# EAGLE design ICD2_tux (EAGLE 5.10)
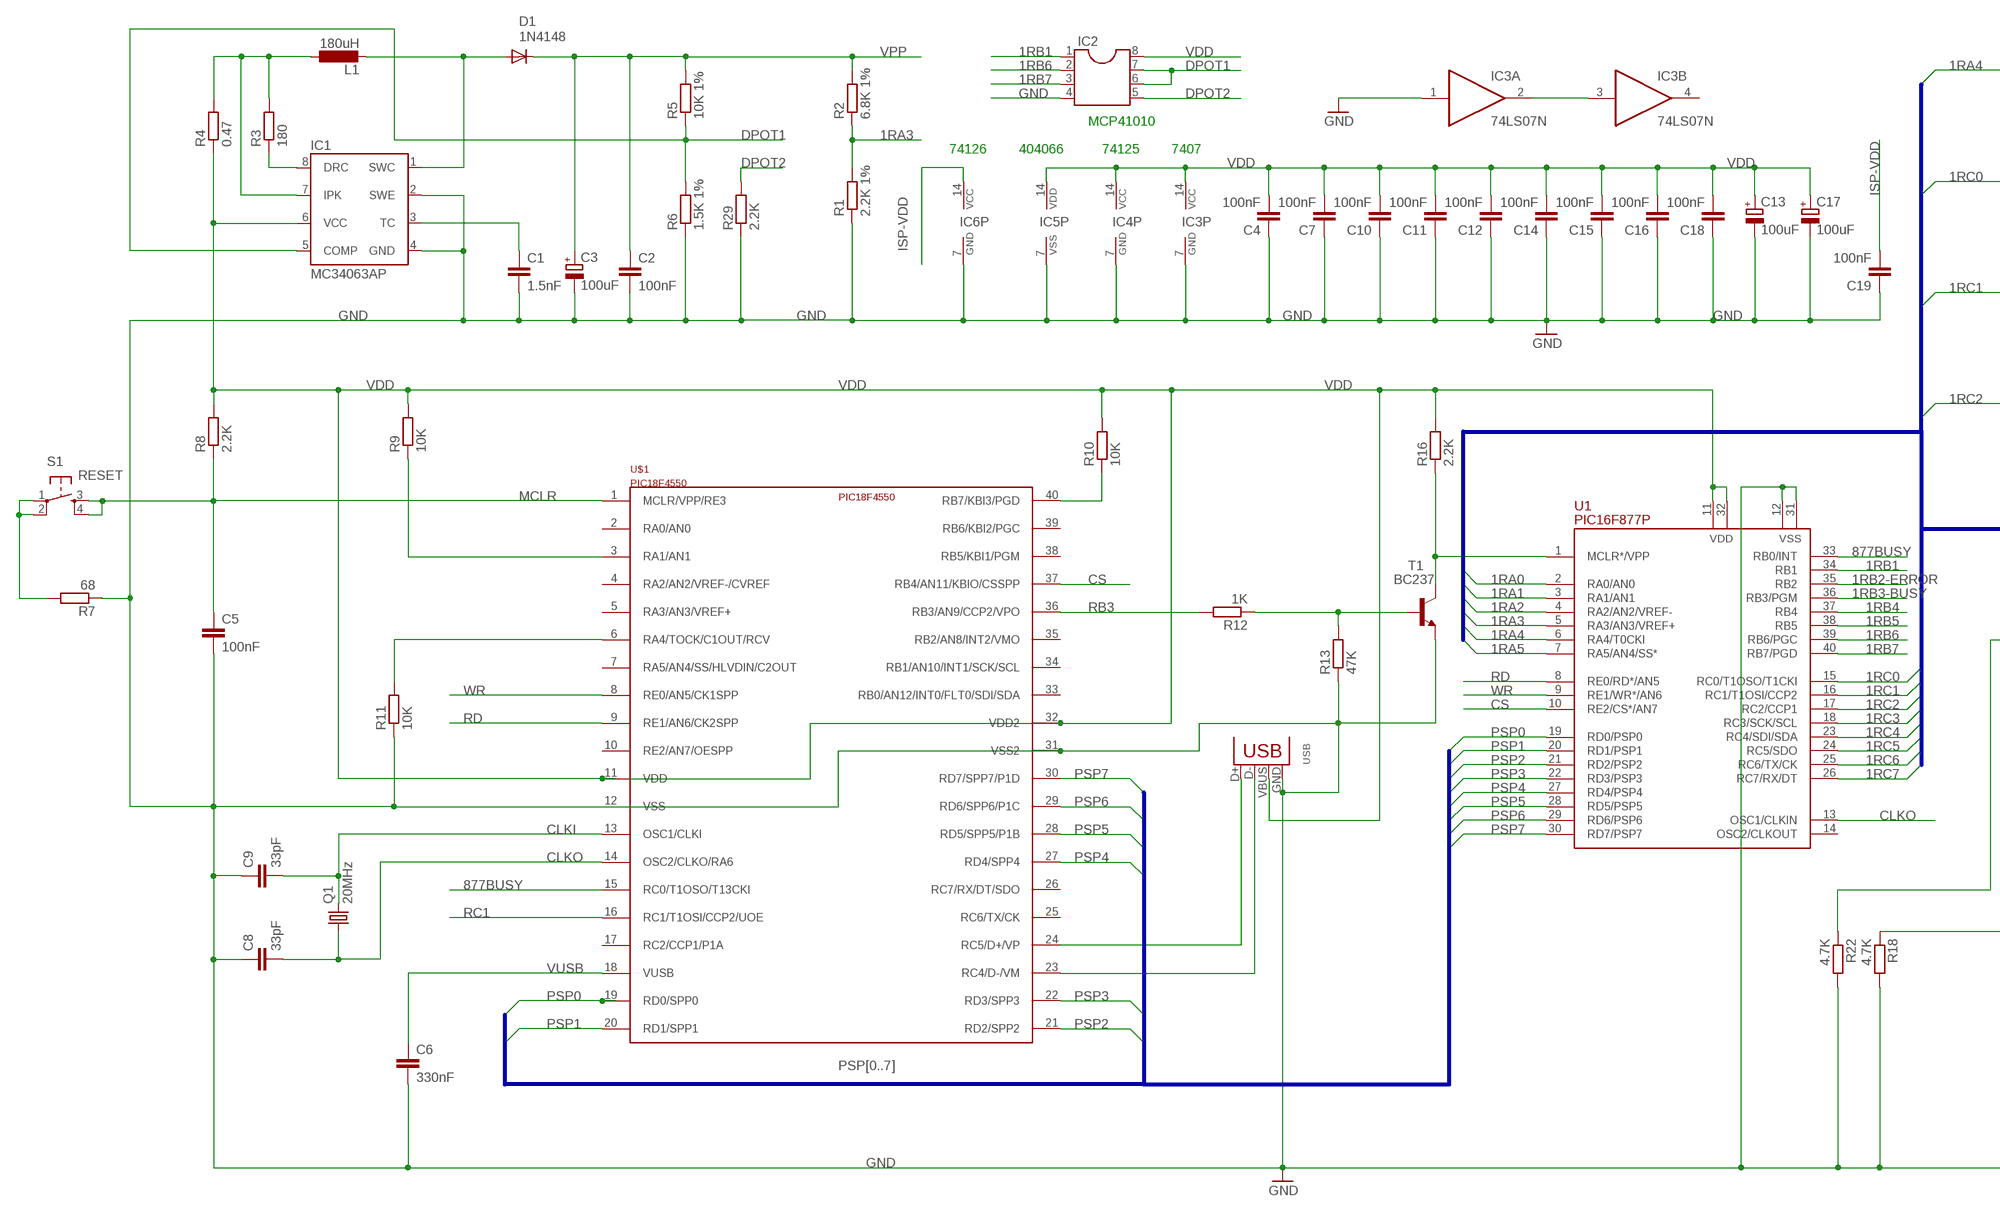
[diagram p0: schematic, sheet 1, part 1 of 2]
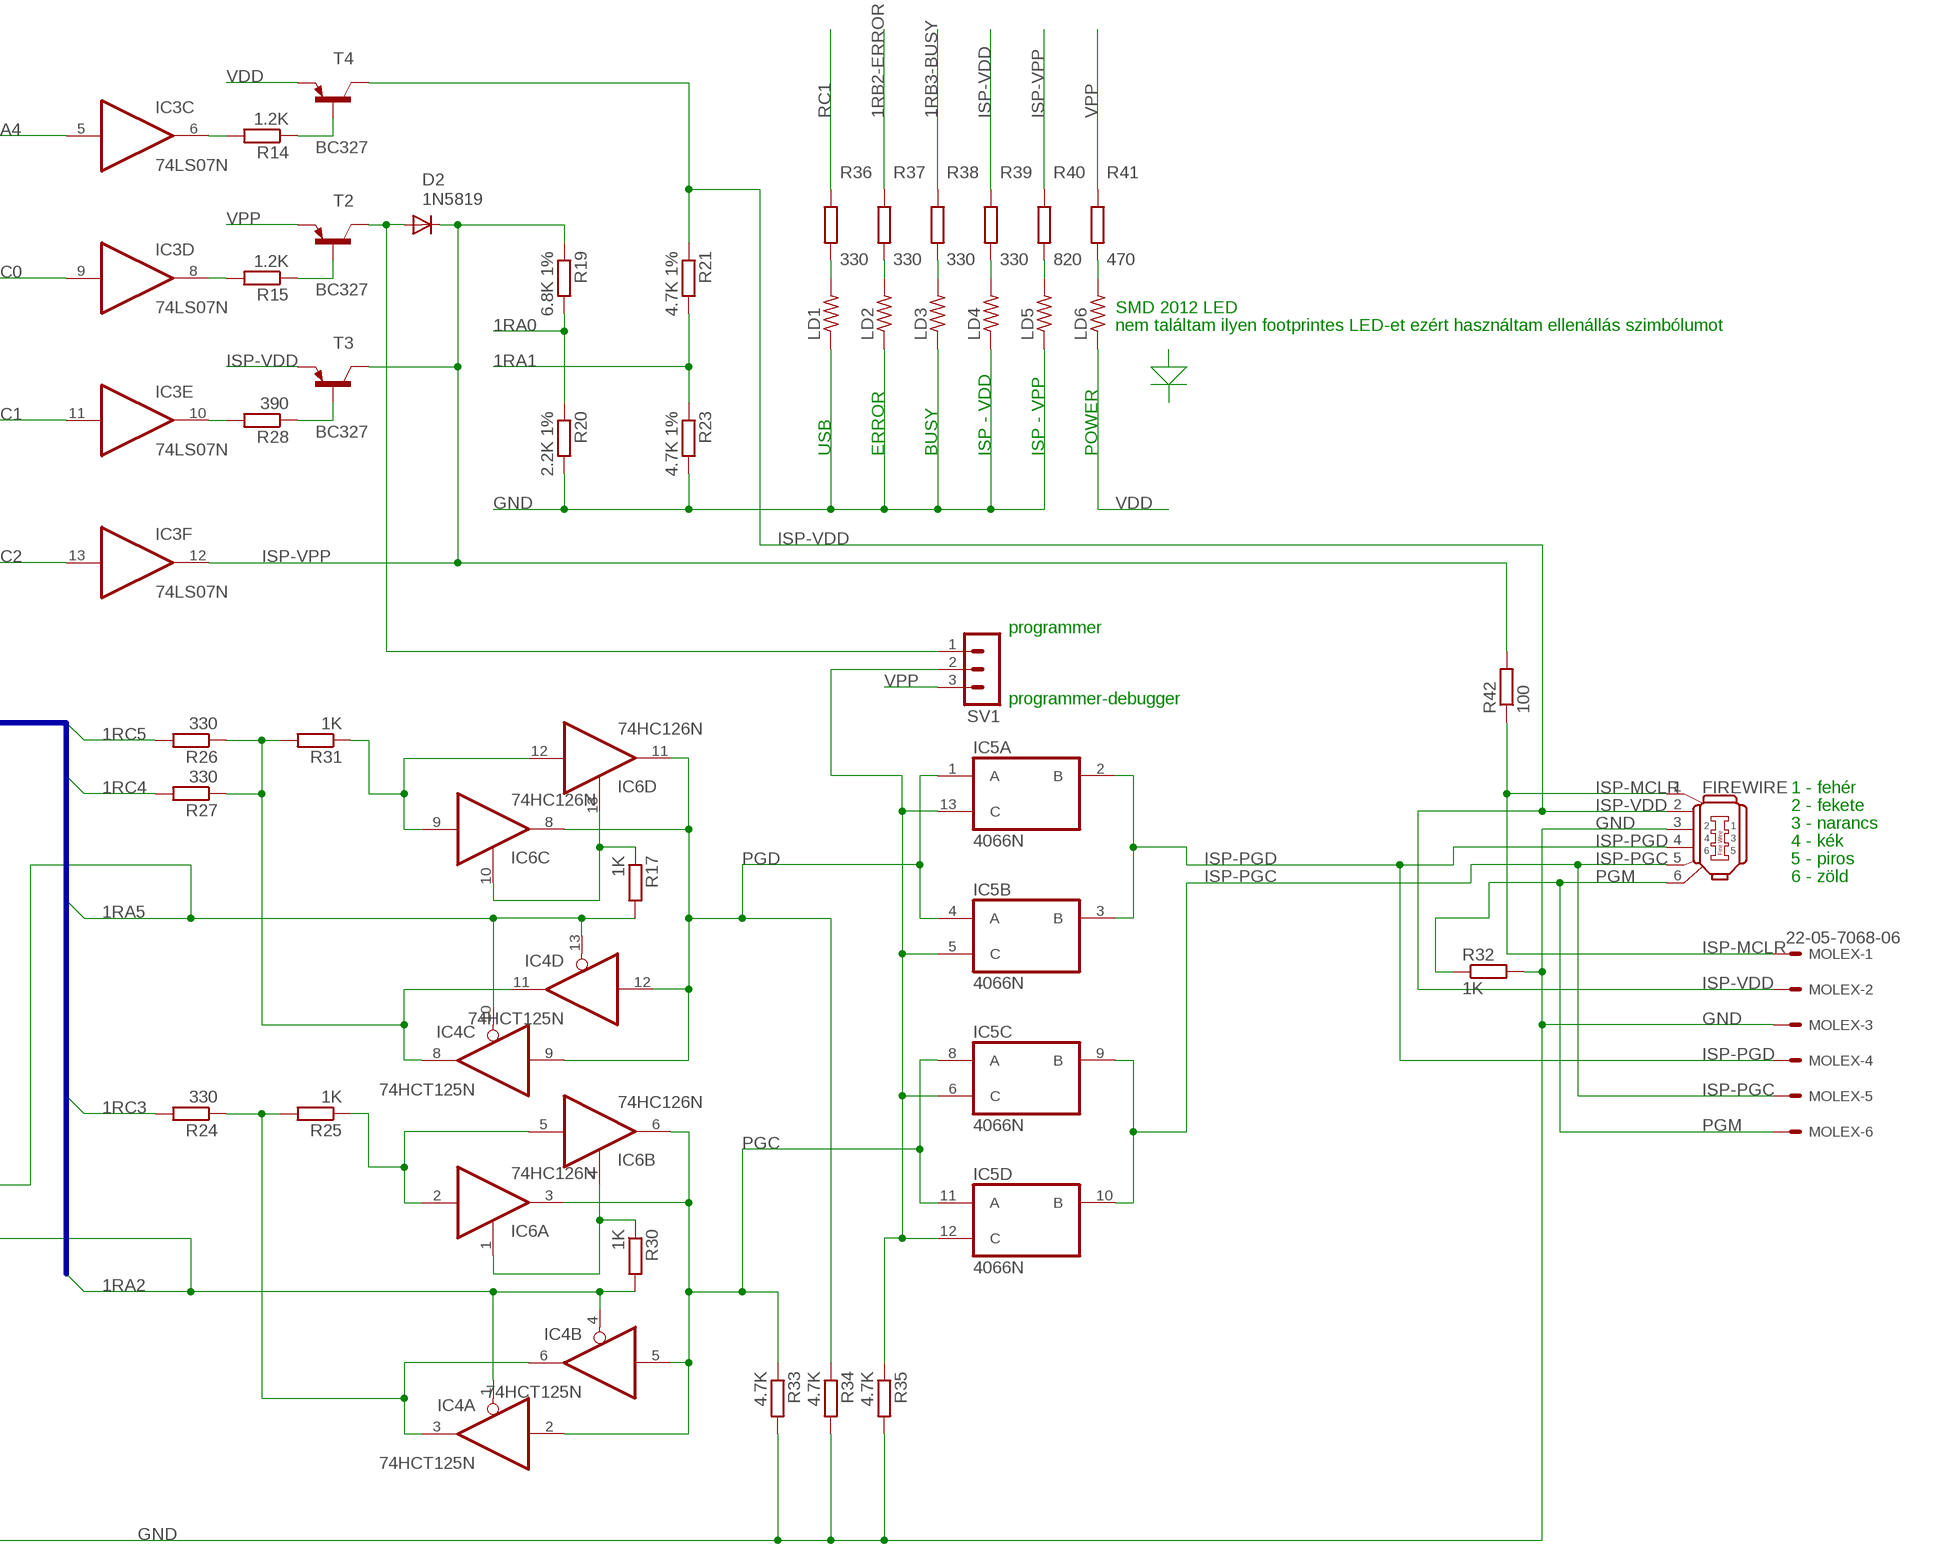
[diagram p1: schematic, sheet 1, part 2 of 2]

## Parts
C1  1.5nF  C-EUC1206  [C1206]
C2  100nF  C-EUC1206  [C1206]
C3  100uF  CPOL-EUE2.5-6  [E2,5-6]
C4  100nF  C-EUC1206  [C1206]
C5  100nF  C-EUC1206  [C1206]
C6  330nF  C-EUC1206  [C1206]
C7  100nF  C-EUC1206  [C1206]
C8  33pF  C-EUC1206  [C1206]
C9  33pF  C-EUC1206  [C1206]
C10  100nF  C-EUC1206  [C1206]
C11  100nF  C-EUC1206  [C1206]
C12  100nF  C-EUC1206  [C1206]
C13  100uF  CPOL-EUE2.5-6  [E2,5-6]
C14  100nF  C-EUC1206  [C1206]
C15  100nF  C-EUC1206  [C1206]
C16  100nF  C-EUC1206  [C1206]
C17  100uF  CPOL-EUE2.5-6  [E2,5-6]
C18  100nF  C-EUC1206  [C1206]
C19  100nF  C-EUC1206  [C1206]
D1  1N4148  DIODE-D-5  [D-5]
D2  1N5819  DIODE-D-5  [D-5]
FIREWIRE  IEEE1394  [IEEE1394]
IC1  MC34063AP  [DIL-08]
IC2  DIL8  [DIL08]
IC3  74LS07N  [DIL14]
IC4  74HCT125N  [DIL14]
IC5  4066N  [DIL14]
IC6  74HC126N  [DIL14]
L1  180uH  L-EU0204/5  [0204/5]
LD1  R-US_M2012  [M2012]
LD2  R-US_M2012  [M2012]
LD3  R-US_M2012  [M2012]
LD4  R-US_M2012  [M2012]
LD5  R-US_M2012  [M2012]
LD6  R-US_M2012  [M2012]
MOLEX  22-05-7068-06  [7395-06]
Q1  20MHz  CRYSTALHC49UP  [HC49UP]
R1  2.2K 1%  R-EU_0204/5  [0204/5]
R2  6.8K 1%  R-EU_0204/5  [0204/5]
R3  180  R-EU_0204/5  [0204/5]
R4  0.47  R-EU_0204/5  [0204/5]
R5  10K 1%  R-EU_0204/5  [0204/5]
R6  1.5K 1%  R-EU_0204/5  [0204/5]
R7  68  R-EU_0204/5  [0204/5]
R8  2.2K  R-EU_0204/5  [0204/5]
R9  10K  R-EU_0204/5  [0204/5]
R10  10K  R-EU_0204/5  [0204/5]
R11  10K  R-EU_0204/5  [0204/5]
R12  1K  R-EU_0204/5  [0204/5]
R13  47K  R-EU_0204/5  [0204/5]
R14  1.2K  R-EU_0204/5  [0204/5]
R15  1.2K  R-EU_0204/5  [0204/5]
R16  2.2K  R-EU_0204/5  [0204/5]
R17  1K  R-EU_0204/5  [0204/5]
R18  4.7K  R-EU_0204/5  [0204/5]
R19  6.8K 1%  R-EU_0204/5  [0204/5]
R20  2.2K 1%  R-EU_0204/5  [0204/5]
R21  4.7K 1%  R-EU_0204/5  [0204/5]
R22  4.7K  R-EU_0204/5  [0204/5]
R23  4.7K 1%  R-EU_0204/5  [0204/5]
R24  330  R-EU_0204/5  [0204/5]
R25  1K  R-EU_0204/5  [0204/5]
R26  330  R-EU_0204/5  [0204/5]
R27  330  R-EU_0204/5  [0204/5]
R28  390  R-EU_0204/5  [0204/5]
R29  2.2K  R-EU_0204/5  [0204/5]
R30  1K  R-EU_0204/5  [0204/5]
R31  1K  R-EU_0204/5  [0204/5]
R32  1K  R-EU_0204/5  [0204/5]
R33  4.7K  R-EU_0204/5  [0204/5]
R34  4.7K  R-EU_0204/5  [0204/5]
R35  4.7K  R-EU_0204/5  [0204/5]
R36  330  R-EU_0204/5  [0204/5]
R37  330  R-EU_0204/5  [0204/5]
R38  330  R-EU_0204/5  [0204/5]
R39  330  R-EU_0204/5  [0204/5]
R40  820  R-EU_0204/5  [0204/5]
R41  470  R-EU_0204/5  [0204/5]
R42  100  R-EU_0204/5  [0204/5]
S1  RESET  DTSM-6  [DTSM-6]
SV1  MA03-1  [MA03-1]
T1  BC237  [TO92]
T2  BC327  [TO92]
T3  BC327  [TO92]
T4  BC327  [TO92]
U1  PIC16F877P  [DIL40]
U$1  PIC18F4550  [PDIP-40]
USB  USB  USB-MB-S  [USB-MB-S]

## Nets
1RA0: R19.2 R20.1 U1.2(RA0/AN0)
1RA1: R21.2 R23.1 U1.3(RA1/AN1)
1RA2: IC4.1(A:OE) IC4.4(B:OE) R18.1 R30.2 U1.4(RA2/AN2/VREF-)
1RA3: R1.2 R2.1 U1.5(RA3/AN3/VREF+)
1RA4: IC3.5(C:I) U1.6(RA4/T0CKI)
1RA5: IC4.10(C:OE) IC4.13(D:OE) R17.2 R22.1 U1.7(RA5/AN4/SS*)
1RB1: IC2.1 U1.34(RB1)
1RB2-ERROR: R37.1 U1.35(RB2)
1RB3-BUSY: R38.1 U1.36(RB3/PGM)
1RB4: U1.37(RB4)
1RB5: U1.38(RB5)
1RB6: IC2.2 U1.39(RB6/PGC)
1RB7: IC2.3 U1.40(RB7/PGD)
1RC0: IC3.9(D:I) U1.15(RC0/T1OSO/T1CKI)
1RC1: IC3.11(E:I) U1.16(RC1/T1OSI/CCP2)
1RC2: IC3.13(F:I) U1.17(RC2/CCP1)
1RC3: R24.2 U1.18(RC3/SCK/SCL)
1RC4: R27.2 U1.23(RC4/SDI/SDA)
1RC5: R26.2 U1.24(RC5/SDO)
1RC6: U1.25(RC6/TX/CK)
1RC7: U1.26(RC7/RX/DT)
877BUSY: U1.33(RB0/INT) U$1.15(RC0/T1OSO/T13CKI)
CLKI: C9.2 Q1.2 U$1.13(OSC1/CLKI)
CLKO: C8.2 Q1.1 U1.13(OSC1/CLKIN) U$1.14(OSC2/CLKO/RA6)
CS: U1.10(RE2/CS*/AN7) U$1.37(RB4/AN11/KBIO/CSSPP)
DPOT1: IC1.5(COMP) IC2.6 IC2.7 R5.1 R6.2
DPOT2: IC2.5 R29.2
GND: C1.2 C2.2 C3.- C4.1 C5.2 C6.2 C7.1 C8.1 C9.1 C10.1 C11.1 C12.1 C13.- C14.1 C15.1 C16.1 C17.- C18.1 C19.1 FIREWIRE.3 IC1.2(SWE) IC1.4(GND) IC2.4 IC3.1(A:I) IC3.7(P:GND) IC4.7(P:GND) IC5.7(P:VSS) IC6.7(P:GND) LD1.1 LD2.1 LD3.1 LD4.1 LD5.1 MOLEX.3 R1.1 R6.1 R7.1 R11.1 R13.1 R18.2 R20.2 R22.2 R23.2 R29.1 R32.2 R33.2 R34.2 R35.2 T1.1(E) U1.12(VSS) U1.31(VSS) U$1.12(VSS) U$1.31(VSS2) USB.GND
ISP-MCLR: FIREWIRE.1 MOLEX.1 R42.1
ISP-PGC: FIREWIRE.5 IC5.9(C:B) IC5.10(D:B) MOLEX.5
ISP-PGD: FIREWIRE.4 IC5.2(A:B) IC5.3(B:B) MOLEX.4
ISP-VDD: C19.2 FIREWIRE.2 IC6.14(P:VCC) MOLEX.2 R21.1 R39.1 T3.1(E) T4.3(C)
ISP-VPP: D2.C IC3.12(F:O) R19.1 R40.1 R42.2 T3.3(C)
MCLR: C5.1 R8.1 S1.3 S1.4 U$1.1(MCLR/VPP/RE3)
N$1: U$1.24(RC5/D+/VP) USB.D+
N$2: U$1.23(RC4/D-/VM) USB.D-
N$3: R10.1 U$1.40(RB7/KBI3/PGD)
N$4: R11.2 U$1.6(RA4/TOCK/C1OUT/RCV)
N$5: R9.1 U$1.3(RA1/AN1)
N$6: IC1.8(DRC) R3.1
N$7: IC1.7(IPK) L1.1 R3.2 R4.2
N$8: D1.A IC1.1(SWC) L1.2
N$9: IC3.2(A:O) IC3.3(B:I)
N$10: C1.1 IC1.3(TC)
N$11: R7.2 S1.1 S1.2
N$12: R12.1 R13.2 T1.2(B)
N$13: R16.1 T1.3(C) U1.1(MCLR*/VPP)
N$14: IC3.6(C:O) R14.2
N$15: IC3.8(D:O) R15.2
N$16: IC3.10(E:O) R28.2
N$17: D2.A SV1.1 T2.3(C)
N$18: R15.1 T2.2(B)
N$19: R14.1 T4.2(B)
N$21: IC6.10(C:OE) IC6.13(D:OE) R17.1
N$22: LD1.2 R36.2
N$23: LD2.2 R37.2
N$24: LD3.2 R38.2
N$25: LD4.2 R39.2
N$26: LD5.2 R40.2
N$27: LD6.2 R41.2
N$28: IC6.2(A:I) IC6.5(B:I) R25.1
N$29: IC6.9(C:I) IC6.12(D:I) R31.1
N$31: IC5.5(B:C) IC5.6(C:C) IC5.12(D:C) IC5.13(A:C) R35.1 SV1.2
N$32: IC6.1(A:OE) IC6.4(B:OE) R30.1
N$33: IC4.8(C:O) IC4.11(D:O) R26.1 R27.1 R31.2
N$37: IC4.3(A:O) IC4.6(B:O) R24.1 R25.2
PGC: IC4.2(A:I) IC4.5(B:I) IC5.8(C:A) IC5.11(D:A) IC6.3(A:O) IC6.6(B:O) R33.1
PGD: IC4.9(C:I) IC4.12(D:I) IC5.1(A:A) IC5.4(B:A) IC6.8(C:O) IC6.11(D:O) R34.1
PGM: FIREWIRE.6 MOLEX.6 R32.1
PSP0: U1.19(RD0/PSP0) U$1.19(RD0/SPP0)
PSP1: U1.20(RD1/PSP1) U$1.20(RD1/SPP1)
PSP2: U1.21(RD2/PSP2) U$1.21(RD2/SPP2)
PSP3: U1.22(RD3/PSP3) U$1.22(RD3/SPP3)
PSP4: U1.27(RD4/PSP4) U$1.27(RD4/SPP4)
PSP5: U1.28(RD5/PSP5) U$1.28(RD5/SPP5/P1B)
PSP6: U1.29(RD6/PSP6) U$1.29(RD6/SPP6/P1C)
PSP7: U1.30(RD7/PSP7) U$1.30(RD7/SPP7/P1D)
R28: R28.1 T3.2(B)
RB3: R12.2 U$1.36(RB3/AN9/CCP2/VPO)
RC1: R36.1 U$1.16(RC1/T1OSI/CCP2/UOE)
RD: U1.8(RE0/RD*/AN5) U$1.9(RE1/AN6/CK2SPP)
VDD: C4.2 C7.2 C10.2 C11.2 C12.2 C13.+ C14.2 C15.2 C16.2 C17.+ C18.2 IC1.6(VCC) IC2.8 IC3.14(P:VCC) IC4.14(P:VCC) IC5.14(P:VDD) LD6.1 R4.1 R8.2 R9.2 R10.2 R16.2 T4.1(E) U1.11(VDD) U1.32(VDD) U$1.11(VDD) U$1.32(VDD2) USB.VBUS
VPP: C2.1 C3.+ D1.C R2.2 R5.2 R41.1 SV1.3 T2.1(E)
VUSB: C6.1 U$1.18(VUSB)
WR: U1.9(RE1/WR*/AN6) U$1.8(RE0/AN5/CK1SPP)
Unconnected: IC3.4(B:O) U1.14(OSC2/CLKOUT) U$1.2(RA0/AN0) U$1.4(RA2/AN2/VREF-/CVREF) U$1.5(RA3/AN3/VREF+) U$1.7(RA5/AN4/SS/HLVDIN/C2OUT) U$1.10(RE2/AN7/OESPP) U$1.17(RC2/CCP1/P1A) U$1.25(RC6/TX/CK) U$1.26(RC7/RX/DT/SDO) U$1.33(RB0/AN12/INT0/FLT0/SDI/SDA) U$1.34(RB1/AN10/INT1/SCK/SCL) U$1.35(RB2/AN8/INT2/VMO) U$1.38(RB5/KBI1/PGM) U$1.39(RB6/KBI2/PGC)

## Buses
PSP[0..7]
1RA[0..5],1RC[0..7]

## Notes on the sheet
- MCP41010
- 74126 | 404066 | 74125 | 7407
- SMD 2012 LED
- nem találtam ilyen footprintes LED-et ezért használtam ellenállás szimbólumot
- USB | ERROR | BUSY | ISP - VDD | ISP - VPP | POWER
- programmer
- programmer-debugger
- 1 - fehér
- 2 - fekete
- 3 - narancs
- 4 - kék
- 5 - piros
- 6 - zöld

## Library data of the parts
C1 C2 C4-C12 C14-C16 C18 C19 = rcl:C-EU: CAPACITOR, European symbol
C3 C13 C17 = rcl:CPOL-EU: POLARIZED CAPACITOR, European symbol
D1 D2 = diode:DIODE-: DIODE
FIREWIRE = con-yamaichi:IEEE1394: YAMAICHI CONNECTOR Fire wire
IC1 = v-reg-3:MC34063A: 1.5A Step-Up/Down/Inverting Switching Regulator NPN Darlington Switch, Vin 3V to 40V, Current Limiter Input, adjustable Frequency up to 100kHz
IC2 = ic-package:DIL8: Dual In Line / Socket
IC3 = 74xx-eu:74*07: Hex BUFFER, open collector high-voltage output
IC4 = 74xx-eu:74*125: Quad bus BUFFER, 3-state
IC5 = 40xx:4066: Quad bilateral ANALOG SWITCH
IC6 = 74xx-eu:74*126: Quad bus BUFFER, 3-state
L1 = rcl:L-EU: INDUCTOR, European symbol
LD1-LD6 = rcl:R-US_: RESISTOR, American symbol
MOLEX = con-molex:22-?-06: CONNECTOR wire to board 2.54 mm (.1 inch) pitch header
Q1 = crystal:CRYSTAL: CRYSTAL
R1-R42 = rcl:R-EU_: RESISTOR, European symbol
S1 = switch-tact:DTSM-6
SV1 = con-lstb:MA03-1: PIN HEADER
T1 = transistor-npn:BC237: NPN Transistor
T2-T4 = transistor-pnp:BC327: PNP Transistor
U1 = pic16f87x:PIC16F877: FLASH MICROCONTROLLER
U$1 = pic18f4550:PIC18F4550
USB = con-usb-3:USB: USB Connectors

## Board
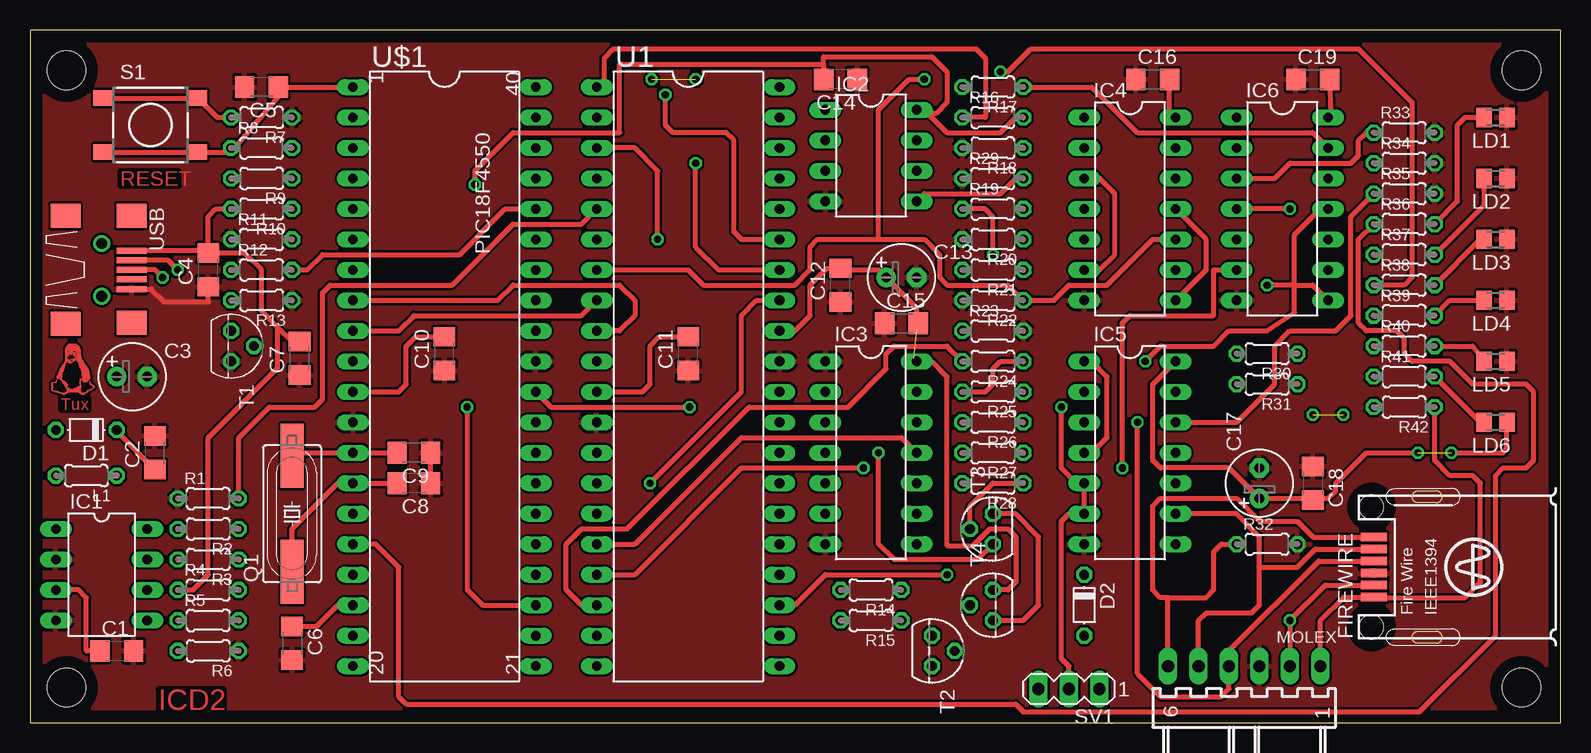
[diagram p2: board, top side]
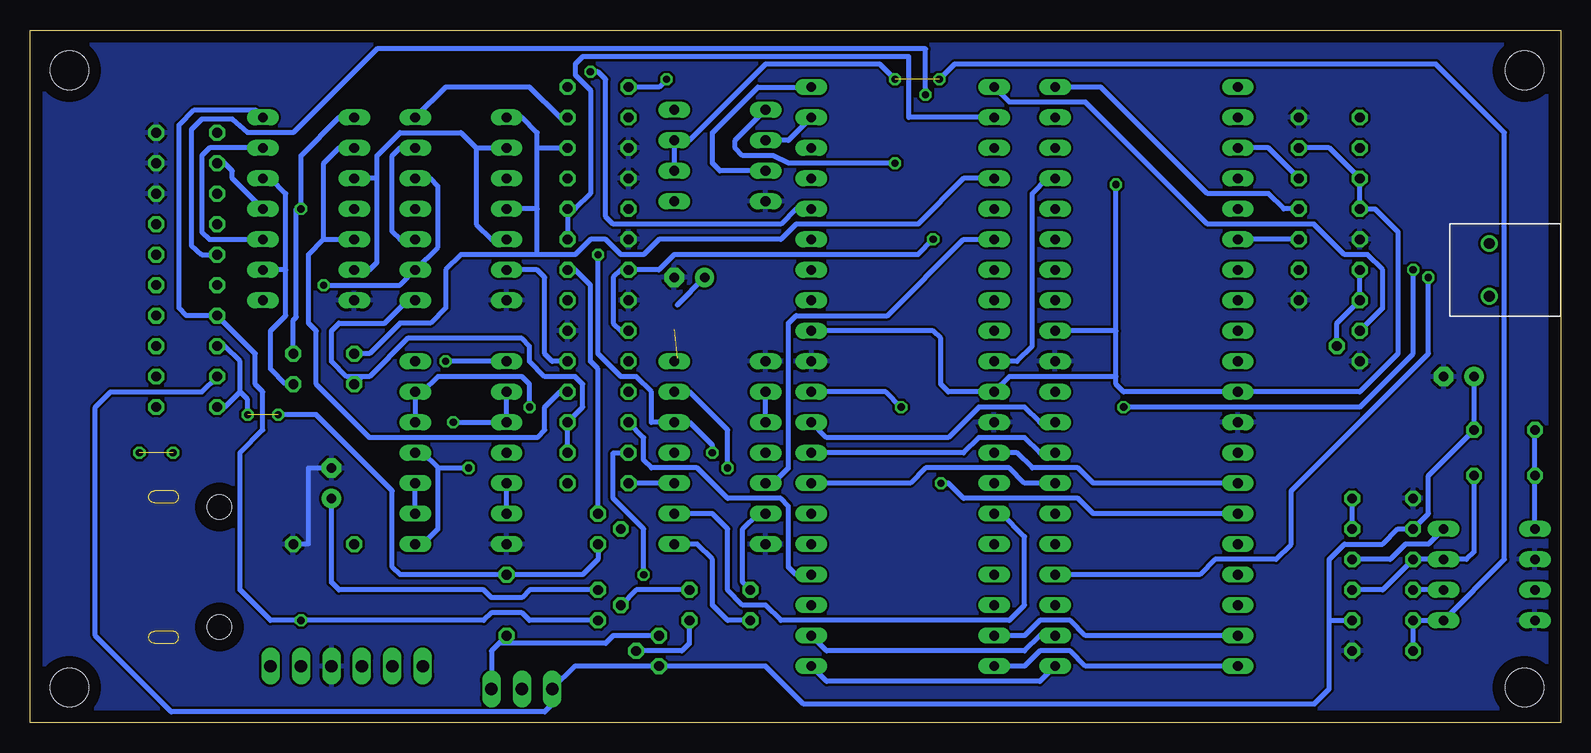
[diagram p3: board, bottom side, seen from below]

Size 127.61 x 57.71 mm. Coordinates in mm from the lower left corner, seen from the top.
Outline: 0,0 127.61,0 127.61,57.71 0,57.71 0,0
Copper layers (1*16): Top 0.035mm / dielectric 1.5mm / Bottom 0.035mm
Design rules "default": minimum track width 10mil, minimum drill 24mil, track to track 8mil, track to pad 8mil, pad to pad 8mil, via to via 8mil, smd to smd 8mil, copper to edge 40mil, drill to drill 8mil, minimum pad ring 10mil, minimum via ring 8mil, stop-mask expansion 4mil, vias tented up to drill 0mil, thermal gap 10mil
Holes 3.2 mm at 3.05,54.36 3.05,2.92 124.33,54.36 124.33,2.92

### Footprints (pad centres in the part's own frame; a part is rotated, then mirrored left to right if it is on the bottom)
C1206 = smd 1.6 x 1.8: 1 -1.4,0; 2 1.4,0
E2,5-6 = drill 0.813 pad 1.6 round: + -1.27,0 | drill 0.813 pad 1.6 octagon: - 1.27,0
D-5 = drill 0.813 octagon: A 2.54,0; C -2.54,0
IEEE1394 = smd 0.7 x 2.2: 1 -2.5,8.25; 2 -1.5,8.25; 3 -0.5,8.25; 4 0.5,8.25; 5 1.5,8.25; 6 2.5,8.25 | hole 2: -5,8.45; 5,8.45
DIL-08 = drill 0.813 long: 1 -3.81,-3.81; 2 -1.27,-3.81; 3 1.27,-3.81; 4 3.81,-3.81; 5 3.81,3.81; 6 1.27,3.81; 7 -1.27,3.81; 8 -3.81,3.81
DIL08 = drill 0.813 long: 1 -3.81,-3.81; 2 -1.27,-3.81; 3 1.27,-3.81; 4 3.81,-3.81; 5 3.81,3.81; 6 1.27,3.81; 7 -1.27,3.81; 8 -3.81,3.81
DIL14 = drill 0.813 long: 1 -7.62,-3.81; 2 -5.08,-3.81; 3 -2.54,-3.81; 4 0,-3.81; 5 2.54,-3.81; 6 5.08,-3.81; 7 7.62,-3.81; 8 7.62,3.81; 9 5.08,3.81; 10 2.54,3.81; 11 0,3.81; 12 -2.54,3.81; 13 -5.08,3.81; 14 -7.62,3.81
0204/5 = drill 0.813 octagon: 1 -2.54,0; 2 2.54,0
M2012 = smd 1.3 x 1.6: 1 -0.95,0; 2 0.95,0
7395-06 = drill 1.016 long: 1 6.35,0; 2 3.81,0; 3 1.27,0; 4 -1.27,0; 5 -3.81,0; 6 -6.35,0
HC49UP = smd 5.334 x 1.93: 1 -4.826,0; 2 4.826,0
DTSM-6 = smd 1.55 x 1.3: 1 -3.975,2.25; 2 3.975,2.25; 3 -3.975,-2.25; 4 3.975,-2.25
MA03-1 = drill 1.016 long: 1 -2.54,0; 2 0,0; 3 2.54,0
TO92 = drill 0.813 octagon: 1 1.27,0; 2 0,1.905; 3 -1.27,0
DIL40 = drill 0.813 long: 1 -24.13,-7.62; 2 -21.59,-7.62; 3 -19.05,-7.62; 4 -16.51,-7.62; 5 -13.97,-7.62; 6 -11.43,-7.62; 7 -8.89,-7.62; 8 -6.35,-7.62; 9 -3.81,-7.62; 10 -1.27,-7.62; 11 1.27,-7.62; 12 3.81,-7.62; 13 6.35,-7.62; 14 8.89,-7.62; 15 11.43,-7.62; 16 13.97,-7.62; 17 16.51,-7.62; 18 19.05,-7.62; 19 21.59,-7.62; 20 24.13,-7.62; 21 24.13,7.62; 22 21.59,7.62; 23 19.05,7.62; 24 16.51,7.62; 25 13.97,7.62; 26 11.43,7.62; 27 8.89,7.62; 28 6.35,7.62; 29 3.81,7.62; 30 1.27,7.62; 31 -1.27,7.62; 32 -3.81,7.62; 33 -6.35,7.62; 34 -8.89,7.62; 35 -11.43,7.62; 36 -13.97,7.62; 37 -16.51,7.62; 38 -19.05,7.62; 39 -21.59,7.62; 40 -24.13,7.62
PDIP-40 = drill 0.813 long: 1 -19.05,-8.89; 2 -16.51,-8.89; 3 -13.97,-8.89; 4 -11.43,-8.89; 5 -8.89,-8.89; 6 -6.35,-8.89; 7 -3.81,-8.89; 8 -1.27,-8.89; 9 1.27,-8.89; 10 3.81,-8.89; 11 6.35,-8.89; 12 8.89,-8.89; 13 11.43,-8.89; 14 13.97,-8.89; 15 16.51,-8.89; 16 19.05,-8.89; 17 21.59,-8.89; 18 24.13,-8.89; 19 26.67,-8.89; 20 29.21,-8.89; 21 29.21,6.35; 22 26.67,6.35; 23 24.13,6.35; 24 21.59,6.35; 25 19.05,6.35; 26 16.51,6.35; 27 13.97,6.35; 28 11.43,6.35; 29 8.89,6.35; 30 6.35,6.35; 31 3.81,6.35; 32 1.27,6.35; 33 -1.27,6.35; 34 -3.81,6.35; 35 -6.35,6.35; 36 -8.89,6.35; 37 -11.43,6.35; 38 -13.97,6.35; 39 -16.51,6.35; 40 -19.05,6.35
USB-MB-S = smd 2.5 x 0.5: D+ 2.5,0; D- 2.5,0.8; GND 2.5,-1.6; ID 2.5,-0.8; VBUS 2.5,1.6 | smd 2.5 x 2: P$1 -3,-4.5; P$2 -3,4.5; P$3 2.5,-4.4; P$4 2.5,4.5 | drill 0.9 round: P$5 0,2.2; P$6 0,-2.2

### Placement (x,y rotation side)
C1  7.24,5.97 0 top
C2  10.41,22.48 90 top
C3  8.51,28.83 0 top
C4  14.86,37.72 90 top
C5  19.3,52.96 180 top
C6  21.84,6.6 270 top
C7  22.48,30.35 90 top
C8  32,19.94 180 top
C9  32,22.48 180 top
C10  34.54,30.73 90 top
C11  54.86,30.73 90 top
C12  67.56,36.45 90 top
C13  72.64,37.08 0 top
C14  67.56,53.59 180 top
C15  72.64,33.27 0 top
C16  93.6,53.59 0 top
C17  102.49,19.94 90 top
C18  106.93,19.94 270 top
C19  106.93,53.59 0 top
D1  4.7,24.38 180 top
D2  87.88,9.78 270 top
FIREWIRE  120.27,12.95 90 top
IC1  5.97,12.32 270 top
IC2  70.1,47.24 270 top
IC3  70.1,22.48 270 top
IC4  91.69,42.8 270 top
IC5  91.69,22.48 270 top
IC6  104.39,42.8 270 top
L1  4.7,20.57 180 top
LD1  122.17,50.42 180 top
LD2  122.17,45.34 180 top
LD3  122.17,40.26 180 top
LD4  122.17,35.18 180 top
LD5  122.17,30.1 180 top
LD6  122.17,25.02 180 top
MOLEX  101.22,4.7 0 top
Q1  21.84,17.4 90 top
R1  14.86,18.67 0 top
R2  14.86,16.13 180 top
R3  14.86,13.59 180 top
R4  14.86,11.05 0 top
R5  14.86,8.51 0 top
R6  14.86,5.97 180 top
R7  19.3,50.42 180 top
R8  19.3,47.88 0 top
R9  19.3,45.34 180 top
R10  19.3,42.8 180 top
R11  19.3,40.26 0 top
R12  19.3,37.72 0 top
R13  19.3,35.18 180 top
R14  70.1,11.05 180 top
R15  70.1,8.51 180 top
R16  80.26,50.42 0 top
R17  80.26,52.96 180 top
R18  80.26,47.88 180 top
R19  80.26,42.8 0 top
R20  80.26,40.26 180 top
R21  80.26,37.72 180 top
R22  80.26,35.18 180 top
R23  80.26,32.64 0 top
R24  80.26,30.1 180 top
R25  80.26,27.56 180 top
R26  80.26,25.02 180 top
R27  80.26,22.48 180 top
R28  80.26,19.94 180 top
R29  80.26,45.34 0 top
R30  103.12,30.73 180 top
R31  103.12,28.19 180 top
R32  103.12,14.86 0 top
R33  114.55,49.15 0 top
R34  114.55,46.61 0 top
R35  114.55,44.07 0 top
R36  114.55,41.53 0 top
R37  114.55,38.99 0 top
R38  114.55,36.45 0 top
R39  114.55,33.91 0 top
R40  114.55,31.37 0 top
R41  114.55,28.83 0 top
R42  114.55,26.29 180 top
S1  10.03,49.78 0 top
SV1  86.61,2.79 180 top
T1  16.76,31.37 270 top
T2  75.18,5.97 270 top
T3  80.26,16.13 90 top
T4  80.26,9.78 90 top
U1  54.86,28.83 270 top
U$1  35.81,33.91 270 top
USB  5.97,37.72 0 top

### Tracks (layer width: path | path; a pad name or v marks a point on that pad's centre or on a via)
1RA0
  Bottom 0.406: U1.2 54.36,50.42 54.36,55.5 81.53,55.5 82.17,54.86 82.17,53.98 80.9,52.71 80.9,44.07 82.17,42.8 R19.2 R20.1
1RA1  (via drill 0.6)
  Top 0.406: v52.32,40.26 52.32,45.97 50.42,47.88 U1.3
  Bottom 0.406: R23.1 78.36,32.64 78.99,33.27 78.99,37.08 78.36,37.72 R21.2 75.18,37.72 73.91,38.99 53.59,38.99 v52.32,40.26
1RA2
  Bottom 0.406: 85.34,42.8 IC4.4 | 85.34,42.8 85.34,47.88 | 85.34,47.88 R18.1 | 85.34,38.99 85.34,42.8 | 85.34,38.99 82.17,38.99 80.9,40.26 79.63,40.26 78.36,38.99 76.45,38.99 75.18,40.26 65.02,40.26 63.75,41.53 53.59,41.53 49.78,45.34 U1.4 | R30.2 99.31,30.73 96.77,33.27 94.23,33.27 92.96,34.54 92.96,37.72 91.69,38.99 85.34,38.99 | IC4.1 86.61,50.42 85.34,49.15 85.34,47.88
1RA3
  Top 0.406: R1.2 17.4,23.75 19.94,26.29 23.75,26.29 24.38,26.92 24.38,35.81 25.02,36.45 35.18,36.45 40.26,41.53 45.97,41.53 U1.5
  Bottom 0.406: R2.1 R1.2
1RA4
  Bottom 0.406: IC3.5 65.66,19.94 64.39,21.21 64.39,33.27 63.75,33.91 56.13,33.91 49.78,40.26 U1.6
1RA5  (via drill 0.6)
  Top 0.406: IC4.10 93.6,40.26 89.79,36.45 86.61,36.45 85.34,35.18 R22.1 81.53,36.45 76.45,36.45 75.82,37.08 75.82,38.99 74.55,40.26 70.74,40.26 | U1.7 54.86,37.72 56.13,36.45 63.75,36.45 65.02,37.72 65.02,39.62 65.66,40.26 70.74,40.26 | v74.55,53.59 73.28,53.59 70.74,51.05 70.74,40.26
  Bottom 0.406: IC4.10 96.77,40.26 97.41,40.89 97.41,47.24 96.77,47.88 IC4.13 | R17.2 75.18,52.96 v74.55,53.59
1RB1  (via drill 0.6)
  Top 0.406: v55.5,46.61 55.5,39.62 57.4,37.72 U1.34
  Bottom 0.406: IC2.1 68.83,48.51 68.83,47.88 68.2,47.24 65.66,47.24 64.39,46.61 v55.5,46.61
1RB2-ERROR  (via drill 0.6)
  Top 0.406: v52.96,52.32 52.96,49.78 53.59,49.15 58.04,49.15 58.67,48.51 58.67,40.89 59.31,40.26 U1.35
  Bottom 0.406: R37.1 113.28,38.99 114.17,39.75 114.17,49.4 113.28,50.29 110.74,50.29 109.47,49.15 105.66,49.15 98.68,56.13 52.96,56.13 v52.96,52.32
1RB3-BUSY  (via drill 0.6)
  Top 0.406: v80.9,54.23 81.53,54.23 83.44,56.13 110.74,56.13 115.19,51.69 115.19,37.08 114.55,36.45 R38.1
  Bottom 0.406: U1.36 63.75,42.8 65.02,41.53 78.99,41.53 79.63,42.16 79.63,53.59 80.26,54.23 v80.9,54.23
1RB6
  Bottom 0.406: IC2.2 64.39,48.51 U1.39
1RB7
  Bottom 0.406: U1.40 66.93,52.96 70.74,49.15 70.74,46.61 70.1,45.97 IC2.3
1RC0
  Bottom 0.406: U1.15 46.61,17.4 44.7,15.49 44.7,9.78 45.97,8.51 65.02,8.51 66.29,9.78 68.2,9.78 69.47,11.05 69.47,16.13 70.74,17.4 IC3.9
1RC1
  Top 0.406: U1.16 50.42,14.86 59.31,23.75 72.64,23.75 IC3.11
1RC2  (via drill 0.6)
  Top 0.406: v69.47,21.21 59.31,21.21 50.42,12.32 U1.17
  Bottom 0.406: IC3.13 72.64,27.56 69.47,24.38 v69.47,21.21
1RC3
  Top 0.406: U1.18 45.97,9.78 44.7,11.05 44.7,14.86 45.97,16.13 49.78,16.13 59.94,26.29 68.2,26.29 71.37,29.46 71.37,30.73 72.01,31.37 76.45,31.37 R24.2
1RC4  (via drill 0.6)
  Top 0.406: v76.45,12.32 66.29,12.32 63.75,9.78 U1.23
  Bottom 0.406: R27.2 78.99,22.48 78.99,18.67 76.45,16.13 v76.45,12.32
1RC5
  Bottom 0.406: R26.2 76.45,23.75 76.45,21.84 75.82,21.21 72.01,21.21 69.47,18.67 65.02,18.67 64.39,18.03 64.39,12.95 63.75,12.32 U1.24
877BUSY  (via drill 0.6)
  Top 0.406: v51.69,19.94 59.31,27.56 59.31,33.91 60.58,35.18 U1.33
  Bottom 0.406: U$1.15 38.99,17.4 40.26,18.67 49.78,18.67 51.05,19.94 v51.69,19.94
CLKI
  Top 0.406: Q1.2 22.1,22.48 U$1.13 C9.2
CLKO
  Top 0.406: Q1.1 21.84,16.13 25.65,19.94 U$1.14 C8.2
  Bottom 0.406: U1.13 45.34,22.48 44.07,21.21 40.26,21.21 38.99,19.94 U$1.14
CS
  Bottom 0.406: U$1.37 42.8,45.34 44.07,44.07 44.07,31.37 45.34,30.1 U1.10
DPOT1  (via drill 0.6)  (1 unrouted)
  Bottom 0.406: R6.2 R5.1 IC1.5 4.7,13.59 4.7,49.15 10.41,54.86 50.55,54.86 v51.82,53.59 | IC2.6 IC2.7 72.64,48.51 66.29,54.86 56.77,54.86 v55.5,53.59
DPOT2
  Top 0.406: R29.2 82.17,45.34 80.9,44.07 74.55,44.07 IC2.5
GND
  Top 0.406: C8.1 C9.1 | USB.GND 10.11,36.12 11.18,35.05 14.86,35.05 C4.1
  Bottom 0.406: R32.2 104.39,14.86 104.39,21.21 C17.-
  pour Top: 0.38,57.4 0.38,0.38 127.13,0.38 127.13,57.4
  pour Bottom: -0.38,58.04 -0.38,-0.38 127.89,-0.38 127.89,58.04
ISP-MCLR
  Top 0.406: R42.1 117.09,21.84 118.36,20.57 120.27,20.57 120.9,19.94 120.9,11.68 119.63,10.41 112.06,10.41 FIREWIRE.1 109.51,10.45 107.57,8.51 MOLEX.1
ISP-PGC
  Top 0.406: MOLEX.5 97.41,8.51 98.04,9.14 101.85,9.14 102.49,9.78 102.49,12.95 | 102.49,12.95 102.49,15.49 100.58,17.4 IC5.9 | FIREWIRE.5 107.16,14.45 105.66,12.95 102.49,12.95
  Bottom 0.406: IC5.9 IC5.10
ISP-PGD  (via drill 0.6)
  Top 0.406: v92.33,25.02 92.33,4.06 94.23,2.16 99.31,2.16 99.95,2.79 MOLEX.4 99.95,5.97 107.43,13.45 FIREWIRE.4
  Bottom 0.406: IC5.2 IC5.3 v92.33,25.02
ISP-VDD  (via drill 0.6)
  Top 0.406: FIREWIRE.2 107.97,11.45 v105.03,8.51 MOLEX.2 | T3.1 82.17,17.4 84.07,15.49 84.07,9.78 82.8,8.51 T4.3 | IC6.14 108.46,50.68 C19.2
  Bottom 0.406: T3.1 80.26,29.46 80.9,30.1 80.9,36.45 82.17,37.72 R21.1 | T4.3 85.98,8.51 86.61,9.14 89.15,9.14 89.79,8.51 v105.03,8.51 107.57,8.51 110.11,11.05 110.11,22.48 108.2,24.38 108.2,27.56 108.84,28.19 108.84,30.73 R39.1 114.55,33.91 115.19,34.54 115.19,49.78 113.92,51.05 108.84,51.05 IC6.14
  other vias: 108.2,50.42
ISP-VPP  (via drill 0.6)  (1 unrouted)
  Top 0.406: v70.74,22.48 70.74,14.86 72.01,13.59 78.99,13.59 T3.3 | R19.1 79.63,42.8 80.26,42.16 v80.26,38.99
  Bottom 0.406: v70.74,22.48 70.74,23.11 72.64,25.02 IC3.12 75.82,25.02 75.82,27.56 77.09,28.83 78.36,28.83 80.26,30.73 v80.26,38.99 | T3.3 80.26,13.59 81.53,12.32 D2.C 96.77,12.32 97.41,12.95 97.41,19.3 103.76,25.65 v106.93,25.65 | R40.1 111.38,31.37 110.11,30.1 110.11,27.56 | 110.11,27.56 111.38,26.29 R42.2 | v109.47,25.65 109.47,26.92 110.11,27.56
MCLR
  Top 0.406: S1.3 S1.4 16.76,47.53 | 16.76,47.53 R8.1 | 16.76,47.53 20.7,52.11 C5.1 U$1.1
N$1  (via drill 0.6)
  Top 0.406: USB.D+ 10.41,37.72 v11.05,37.08
  Bottom 0.406: v11.05,37.08 11.05,30.73 22.48,19.3 22.48,14.86 23.75,13.59 28.83,13.59 30.1,12.32 U$1.24
N$2  (via drill 0.6)
  Top 0.406: USB.D- 11.52,38.52 v12.32,37.72 | v36.45,26.29 36.45,11.05 37.72,9.78 U$1.23
  Bottom 0.406: v12.32,37.72 12.32,30.73 16.76,26.29 v36.45,26.29
N$3
  Bottom 0.406: R10.1 23.11,42.8 24.38,44.07 29.46,44.07 38.35,52.96 U$1.40
N$4
  Bottom 0.406: R11.2 U$1.6
N$5
  Bottom 0.406: U$1.3 24.38,47.88 R9.1
N$6
  Bottom 0.406: IC1.8 11.05,14.86 12.95,14.86 14.22,13.59 R3.1
N$7
  Bottom 0.406: R4.2 14.86,11.05 R3.2 IC1.7 7.87,13.59 7.24,14.22 L1.1
N$8
  Bottom 0.406: D1.A L1.2 IC1.1
N$9
  Bottom 0.406: IC3.3 IC3.2
N$10
  Top 0.406: C1.1 4.7,5.97 4.7,10.41 4.06,11.05 IC1.3
N$11
  Top 0.406: S1.1 S1.2 15.62,50.42 R7.2
N$12
  Bottom 0.406: R12.1 R13.2 18.67,33.27 T1.2
N$13
  Top 0.406: U1.1 47.88,53.59 47.88,55.37 48.64,56.13 78.87,56.13 79.63,55.37 79.63,50.42 R16.1
  Bottom 0.406: T1.3 14.86,34.54 14.86,37.72 16.13,38.99 18.03,38.99 20.57,41.53 29.46,41.53 39.62,51.69 45.97,51.69 U1.1
N$14
  Bottom 0.406: IC3.6 66.93,17.4 68.2,16.13 68.2,11.68 R14.2
N$15
  Bottom 0.406: R15.2 69.47,8.51 70.74,9.78 70.74,13.59 72.01,14.86 IC3.8
N$16
  Bottom 0.406: IC3.10 R28.2
N$17
  Bottom 0.406: 88.52,6.6 D2.A | SV1.1 89.15,5.97 88.84,6.29 88.52,6.6 | T2.3 78.99,7.24 79.63,6.6 88.52,6.6
N$18
  Bottom 0.406: T2.2 73.28,5.97 72.64,6.6 R15.1
N$19
  Bottom 0.406: R14.1 77.09,11.05 T4.2
N$21
  Top 0.406: R17.1 88.52,52.96 92.33,49.15 106.93,49.15 IC6.13
  Bottom 0.406: IC6.10 112.65,40.26 113.28,40.89 113.28,47.24 112.65,47.88 IC6.13
N$22
  Top 0.406: LD1.2 119.63,50.42 119,49.78 119,43.43 R36.2
N$23
  Top 0.406: LD2.2 121.22,43.12 R37.2
N$24
  Top 0.406: LD3.2 120.9,40.26 R38.2
N$25
  Top 0.406: LD4.2 118.36,35.18 R39.2
N$26
  Top 0.406: LD5.2 120.27,31.37 R40.2
N$27
  Top 0.406: LD6.2 120.9,25.02 R41.2
N$28
  Bottom 0.406: 103.12,40.26 IC6.5 | 103.12,40.26 103.12,46.61 101.85,47.88 IC6.2 | R25.1 83.44,27.56 84.71,26.29 84.71,24.38 85.34,23.75 99.31,23.75 103.76,28.19 103.76,32.64 104.39,33.27 104.39,38.99 103.12,40.26
N$29
  Bottom 0.406: R31.1 106.3,28.19 107.57,29.46 107.57,32.64 106.3,33.91 106.3,37.72 | 106.3,37.72 106.3,44.07 107.57,45.34 IC6.12 | 106.3,37.72 IC6.9
N$31  (via drill 0.6)
  Top 0.406: SV1.2 86.61,4.7 85.98,5.33 85.98,16.76 86.61,17.4 IC5.6 IC5.5 87.25,19.94 85.98,21.21 v85.98,26.29 | IC5.12 100.58,25.02 103.76,28.19 103.76,31.37 105.03,32.64 108.84,32.64 110.11,33.91 110.11,42.16 R35.1
  Bottom 0.406: IC5.6 IC5.5 | IC5.12 IC5.13 94.87,27.56 93.6,28.83 86.61,28.83 85.98,28.19 v85.98,26.29
N$32  (via drill 0.6)
  Top 0.406: v105.03,42.8 IC6.4
  Bottom 0.406: R30.1 105.66,33.53 105.41,33.78 105.41,42.8 v105.03,42.8 105.03,47.24 101.85,50.42 IC6.1
N$33
  Top 0.406: IC4.8 98.04,37.72 98.04,40.26 IC4.11
  Bottom 0.406: R27.1 R26.1 81.53,26.29 81.53,28.19 82.17,28.83 84.71,28.83 85.98,30.1 85.98,31.37 86.61,32 96.14,32 99.31,28.83 99.95,28.83 | 99.95,28.83 R31.2 | 99.95,28.83 101.22,28.83 102.49,30.1 102.49,32.64 101.85,33.27 98.04,33.27 96.14,35.18 IC4.8
N$37
  Top 0.406: R25.2 79.63,27.56 80.26,28.19 80.26,29.46 80.9,30.1 R24.1 | IC4.6 89.15,37.72 90.42,38.99 90.42,44.07 89.15,45.34 IC4.3
  Bottom 0.406: R24.1 84.07,30.1 84.71,30.73 84.71,37.08 85.34,37.72 IC4.6
PGC  (via drill 0.6)
  Top 0.406: R33.1 111.38,49.15 110.74,48.51 110.74,47.24 110.11,46.61 105.03,46.61 103.76,45.34 IC6.3 | v91.06,21.21 91.06,33.27 91.69,33.91 98.68,33.91 98.68,37.72 IC6.6
  Bottom 0.406: 90.42,47.88 90.42,41.53 89.15,40.26 IC4.5 | 90.42,47.88 IC4.2 | 90.42,47.88 91.69,49.15 96.77,49.15 98.68,47.24 98.68,45.34 | 98.68,45.34 IC6.3 | IC6.6 99.31,37.72 98.68,38.35 98.68,45.34 | IC5.8 94.87,14.86 93.6,16.13 93.6,21.21 | IC5.11 94.87,22.48 93.6,21.21 | 93.6,21.21 v91.06,21.21
PGD  (via drill 0.6)
  Top 0.406: v92.96,30.1 94.23,31.37 98.68,31.37 99.95,32.64 103.12,32.64 105.41,34.16 105.41,36.45 | 105.41,36.45 v103.12,36.45 | 105.41,36.45 106.93,36.45 IC6.8 | IC6.11 107.57,42.8 105.41,40.64 105.41,36.45 | IC5.1 88.52,30.1 89.79,28.83 89.79,23.75 88.52,22.48 IC5.4
  Bottom 0.406: IC4.12 94.23,45.34 93.6,44.7 93.6,39.62 IC4.9 96.77,36.45 v103.12,36.45 | R34.1 111.38,46.61 110.74,45.97 110.74,45.34 IC6.11 | IC5.1 v92.96,30.1
PGM
  Top 0.406: R32.1 99.31,14.86 98.68,14.22 98.68,11.05 98.04,10.41 94.87,10.41 | MOLEX.6 94.87,10.41 | FIREWIRE.6 106.97,15.45 105.66,16.76 102.49,16.76 100.58,18.67 94.23,18.67 93.6,18.03 93.6,11.05 94.23,10.41 94.87,10.41
PSP0
  Bottom 0.406: U$1.19 39.62,7.24 40.89,8.51 43.43,8.51 44.7,7.24 U1.19
PSP1
  Bottom 0.406: U$1.20 39.62,4.7 40.89,5.97 43.43,5.97 44.7,4.7 U1.20
PSP2
  Bottom 0.406: U$1.21 43.43,3.43 61.21,3.43 U1.21
PSP3
  Bottom 0.406: U$1.22 43.43,7.24 44.7,5.97 61.21,5.97 U1.22
PSP4
  Bottom 0.406: U1.27 54.23,19.94 52.96,21.21 45.97,21.21 44.7,19.94 U$1.27
PSP5
  Bottom 0.406: U$1.28 43.43,22.48 44.7,23.75 48.51,23.75 49.78,22.48 U1.28
PSP6
  Bottom 0.406: U$1.29 43.43,25.02 44.7,26.29 48.51,26.29 51.05,23.75 61.21,23.75 U1.29
PSP7  (via drill 0.6)
  Top 0.406: U$1.30 43.43,26.29 v54.99,26.29
  Bottom 0.406: v54.99,26.29 56.26,27.56 U1.30
R28
  Top 0.406: R28.1 80.26,19.94 78.36,18.03 T3.2
RB3
  Top 0.406: R12.2 23.11,37.72 24.38,38.99 35.81,38.99 39.62,42.8 U$1.36
RC1
  Top 0.406: U$1.16 28.83,14.86 30.73,12.95 30.73,2.16 31.37,1.52 82.17,1.52 82.8,0.89 115.82,0.89 122.17,7.24 122.17,20.57 122.81,21.21 124.71,21.21 125.35,21.84 125.35,27.56 124.71,28.19 120.27,28.19 118.36,30.1 115.19,30.1 114.55,30.73 114.55,32 113.92,32.64 111.38,32.64 110.74,33.27 110.74,40.26 R36.1
RD
  Top 0.406: U$1.9 30.73,32.64 32,33.91 45.97,33.91 U1.8
VDD  (via drill 0.6)  (2 unrouted)
  Top 0.406: USB.VBUS 14.66,39.32 C4.2 | R10.2 15.49,42.8 14.86,42.16 C4.2 | C4.2 17.9,39.12 19.3,37.72 19.3,34.29 20.64,32.96 | R4.1 13.59,11.05 14.86,12.32 14.86,23.75 20.57,29.46 20.64,29.53 20.64,32.96 | 20.64,32.96 21.84,31.75 C7.2 | U$1.11 30.73,27.56 31.37,28.19 31.37,31.37 32.13,32.13 C10.2 34.67,32 | C11.2 52.45,32.13 51.69,31.37 51.69,28.19 51.05,27.56 U1.11 | C15.2 73.91,32.77 73.91,34.54 C13.+ 70.74,37.72 67.69,37.72 C12.2 66.42,37.85 65.02,36.45 65.02,33.91 63.75,32.64 U1.32 | T4.1 81.53,11.05 82.17,11.68 82.17,15.49 81.53,16.13 80.01,16.13 78.61,14.73 76.45,14.73 76.45,28.83 75.18,30.1 IC3.14 | IC5.14 93.6,28.19 93.6,21.84 94.23,21.21 99.95,21.21 C17.+ 106.8,18.67 C18.2 107.06,18.67 108.2,18.67 108.84,19.3 108.84,19.94 111.38,22.48 v115.7,22.48 | LD6.1 123.12,22.79 122.81,22.48 v118.49,22.48 | R16.2 82.17,50.42 80.9,49.15 76.45,49.15 74.87,50.74 | 74.87,50.74 74.55,51.05 IC2.8 | 74.87,50.74 75.5,50.74 76.45,51.69 76.45,54.23 75.18,55.5 66.16,55.5 66.16,54.86 | v37.08,44.83 37.08,45.97 40.26,49.15 49.15,49.15 49.15,54.86 66.16,54.86 | IC4.14 95,50.92 C16.2 | 66.16,54.86 C14.2
  Bottom 0.406: R8.2 19.3,47.88 R9.2 R10.2 15.49,42.8 13.59,40.89 13.59,30.73 16.76,27.56 U$1.11 36.45,27.56 37.08,28.19 37.08,28.83 | IC1.6 R4.1 | 37.08,32.64 U$1.32 | 37.08,28.83 45.97,28.83 U1.11 51.05,27.56 51.69,28.19 51.69,32 52.32,32.64 U1.32 | IC3.14 73.67,30.35 | C13.+ 73.67,34.79 | C17.+ 102.49,11.68 101.85,11.05 89.79,11.05 89.15,10.41 86.61,10.41 85.98,11.05 T4.1 | R16.2 83.44,50.42 85.98,52.96 92.96,52.96 IC4.14 | 37.08,28.83 37.08,32.64 | 37.08,32.64 v37.08,44.83
  other vias: 95.5,50.42
VPP
  Top 0.406: C2.1 7.24,24.25 D1.C
  Bottom 0.406: 19.3,8.51 19.3,13.59 18.03,14.86 14.86,14.86 13.59,16.13 R2.2 11.05,17.4 11.05,20.57 D1.C C3.+ | 19.3,8.51 R5.2 | 19.3,8.51 19.3,2.79 20.57,1.52 63.12,1.52 66.29,4.7 T2.1 82.17,4.7 SV1.3 84.07,1.52 84.71,0.89 115.82,0.89 122.17,7.24 122.17,26.29 120.9,27.56 113.28,27.56 R41.1
VUSB
  Top 0.406: U$1.18 25.65,9.78 23.88,8 C6.1
WR
  Top 0.406: U$1.8 38.99,35.18 40.26,36.45 49.15,36.45 50.42,35.18 50.42,33.91 49.15,32.64 U1.9
(copper drawn outside any net)
  shapes: Top area x241

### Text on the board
Top: RESET | Tux | ICD2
